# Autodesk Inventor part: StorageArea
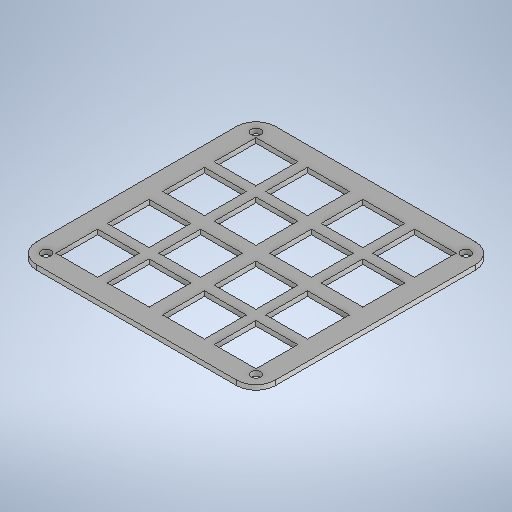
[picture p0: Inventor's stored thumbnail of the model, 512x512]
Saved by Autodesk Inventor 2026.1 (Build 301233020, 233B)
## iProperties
Created: 2026-10
Part Number: StorageArea
Material: Generic
Document SubType Name: Modeling
Designer: hp
Density: 1 g/cm^3
Appearance: Default
Author: hp
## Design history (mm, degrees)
sketch "Sketch1"
  geometry: L1 (384.652, 48.52)-(427.652, 48.52); L2 (427.652, 48.52)-(427.652, 91.52); L3 (427.652, 91.52)-(384.652, 91.52); L4 (384.652, 91.52)-(384.652, 48.52); L5 (384.652, -61.48)-(427.652, -61.48); L6 (427.652, -61.48)-(427.652, -18.48); L7 (427.652, -18.48)-(384.652, -18.48); L8 (384.652, -18.48)-(384.652, -61.48); L9 (494.652, 48.52)-(537.652, 48.52); L10 (537.652, 48.52)-(537.652, 91.52); L11 (537.652, 91.52)-(494.652, 91.52); L12 (494.652, 91.52)-(494.652, 48.52); L13 (494.652, -61.48)-(537.652, -61.48); L14 (537.652, -61.48)-(537.652, -18.48); L15 (537.652, -18.48)-(494.652, -18.48); L16 (494.652, -18.48)-(494.652, -61.48); L17 (494.652, -114.48)-(537.652, -114.48); L18 (537.652, -114.48)-(537.652, -71.48); L19 (384.652, -4.48)-(427.652, -4.48); L20 (494.652, -71.48)-(494.652, -114.48); L21 (427.652, -114.48)-(427.652, -71.48); L22 (427.652, -71.48)-(384.652, -71.48); L23 (384.652, -114.48)-(427.652, -114.48); L24 (384.652, -71.48)-(384.652, -114.48); L25 (384.652, 38.52)-(384.652, -4.48); L26 (427.652, 38.52)-(384.652, 38.52); L27 (427.652, -4.48)-(427.652, 38.52); L28 (537.652, -71.48)-(494.652, -71.48); L29 (494.652, -4.48)-(537.652, -4.48); L30 (494.652, 38.52)-(494.652, -4.48); L31 (537.652, 38.52)-(494.652, 38.52); L32 (537.652, -4.48)-(537.652, 38.52); L33 (547.652, -61.48)-(590.652, -61.48); L34 (590.652, -61.48)-(590.652, -18.48); L35 (437.652, 48.52)-(480.652, 48.52); L36 (547.652, -18.48)-(547.652, -61.48); L37 (480.652, -61.48)-(480.652, -18.48); L38 (480.652, -18.48)-(437.652, -18.48); L39 (437.652, -61.48)-(480.652, -61.48); L40 (437.652, -18.48)-(437.652, -61.48); L41 (437.652, 91.52)-(437.652, 48.52); L42 (480.652, 91.52)-(437.652, 91.52); L43 (480.652, 48.52)-(480.652, 91.52); L44 (590.652, -18.48)-(547.652, -18.48); L45 (547.652, 48.52)-(590.652, 48.52); L46 (547.652, 91.52)-(547.652, 48.52); L47 (590.652, 91.52)-(547.652, 91.52); L48 (590.652, 48.52)-(590.652, 91.52); L49 (547.652, -114.48)-(590.652, -114.48); L50 (590.652, -114.48)-(590.652, -71.48); L51 (437.652, -4.48)-(480.652, -4.48); L52 (547.652, -71.48)-(547.652, -114.48); L53 (480.652, -114.48)-(480.652, -71.48); L54 (480.652, -71.48)-(437.652, -71.48); L55 (437.652, -114.48)-(480.652, -114.48); L56 (437.652, -71.48)-(437.652, -114.48); L57 (437.652, 38.52)-(437.652, -4.48); L58 (480.652, 38.52)-(437.652, 38.52); L59 (480.652, -4.48)-(480.652, 38.52); L60 (590.652, -71.48)-(547.652, -71.48); L61 (547.652, -4.48)-(590.652, -4.48); L62 (547.652, 38.52)-(547.652, -4.48); L63 (590.652, 38.52)-(547.652, 38.52); L64 (590.652, -4.48)-(590.652, 38.52)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; C1 r 5 at (379.652, 96.52); C2 r 5 at (595.652, 96.52); C3 r 5 at (379.652, -119.48); C4 r 5 at (595.652, -119.48); 32 further points
  constraints: 140 end point, 4 centre point, 4 collinear, 4 horizontal, 4 midpoint, 4 parallel, 3 symmetric about line, 2 perpendicular, 2 vertical, 119 other
  dimensions: "d6" = 43 distance of L3.end L2.end; "d7" = 43 distance of L2.end L1.end; "d28" = 110 distance of L1.start L5.start (derived); "d31" = 110 distance of L1.start L9.start; "d36" = 53 distance of L1.end L19.end (computed from d7); "d39" = 53 distance of L1.end L35.end (computed from d7); "d42" = 20 distance between parallel lines of L24 L68; "d43" = 20 distance between parallel lines of L17 L67; "d44" = 20 distance between parallel lines of L64 L66; "d45" = 20 distance between parallel lines of L11 L65; "d47" = 10 diameter of C1; "d48" = 15 distance from line of L65 C1.centre (= d49); "d49" = 15 distance from line of L68 C1.centre
  node "Sketch Rectangular Pattern1" dims "d28" = 110 (derived), "d31" = 110
  node "Sketch Rectangular Pattern2" dims "d36" = 53 (computed from d7), "d39" = 53 (computed from d7)
extrude "Extrusion1" new body sketch "Sketch1" distance "d20" = 5; taper "d21" = 0 deg
fillet "Fillet2" dims "d46" = 20
extrude "Extrusion2" cut sketch "Sketch1" distance "d51" = 10; taper "d52" = 0 deg
body "Solid1"
